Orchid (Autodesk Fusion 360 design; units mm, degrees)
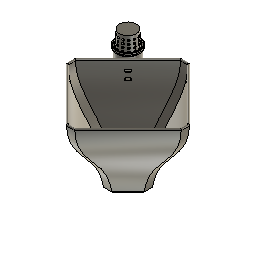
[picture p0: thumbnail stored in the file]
parameter "wall" = 1.35
parameter "height" = 102 (= "Size * 0.6") comment "Vase Hight (Medium setting)"
parameter "tolerance" = 0.15
sketch "Sketch1" plane through (0, 0, 0) normal (0, 0, 1) x axis (1, 0, 0)
  line L1 (-79.0621, -79.0621) -> (79.0621, -79.0621)
  line L2 (-79.0621, 79.0621) -> (-79.0621, -79.0621)
  line L3 (79.0621, 79.0621) -> (-79.0621, 79.0621)
  line L4 (79.0621, -79.0621) -> (79.0621, 79.0621)
  line L5 (-79.0621, 79.0621) -> (79.0621, -79.0621)
  line L6 (79.0621, 79.0621) -> (-79.0621, -79.0621)
  line L7 (-75.5266, 82.5976) -> (82.5976, -75.5266)
  line L8 (-82.5976, 75.5266) -> (75.5266, -82.5976)
  line L9 (-5.9379, 39.9379) -> (28.0621, 5.9379)
  line L10 (-39.9379, 5.9379) -> (-5.9379, 39.9379)
  line L11 (-5.9379, -28.0621) -> (-39.9379, 5.9379)
  line L12 (28.0621, 5.9379) -> (-5.9379, -28.0621)
  line L13 (-39.9379, 5.9379) -> (28.0621, 5.9379)
  line L14 (-5.9379, -28.0621) -> (-5.9379, 39.9379)
  line L15 (-5.9379, 79.0621) -> (-5.9379, 5.9379)
  line L16 (-2.4024, 9.4734) -> (-9.4734, 2.4024)
  line L17 (-60.5266, 67.5976) -> (-67.5976, 60.5266)
  circle C1 centre (-5.9379, 5.9379) radius 85
  circle C2 centre (-64.0621, 64.0621) radius 15
  circle C3 centre (-5.9379, 5.9379) radius 34
  circle C4 centre (-64.0621, 64.0621) radius 13.65
  circle C5 centre (-64.0621, 64.0621) radius 13.5
  circle C6 centre (-5.9379, 5.9379) radius 67.2
  point P6 (0, 0)
  point P1 (0, 0)
  point P7 (-5.9379, 5.9379)
  point P8 (-64.0621, 64.0621)
  point P9 (-5.9379, 5.9379)
  point P19 (-5.9379, 5.9379)
  point P15 (28.0621, 5.9379)
  point P20 (-5.9379, 5.9379)
  point P21 (-5.9379, 79.0621)
  point P22 (-9.4734, 2.4024)
  point P23 (-2.4024, 9.4734)
  point P26 (-5.9379, 5.9379)
  point P27 (-67.5976, 60.5266)
  point P28 (-60.5266, 67.5976)
  point P24 (-64.0621, 64.0621)
  horizontal L1
  perpendicular L1 L2
  parallel L1 L3
  parallel L2 L4
  coincident L5 P6
  coincident L6 P6
  coincident P1 P6
  coincident L5 P7
  coincident L5 P8
  tangent L3 C2
  tangent L4 C1
  coincident P7 P9
  perpendicular L9 L10
  parallel L9 L11
  parallel L10 L12
  coincident L13 P19
  coincident L14 P19
  coincident P9 P19
  equal L9 L12
  coincident C3 P15
  coincident P9 P20
  coincident L3 P21
  perpendicular L3 L15
  coincident L8 P22
  coincident L7 P23
  perpendicular L7 L16
  equal L2 L3
  midpoint P19 L16
  coincident P19 P26
  tangent C2 C6
  coincident L8 P27
  coincident L7 P28
  perpendicular L7 L17
  coincident P24 L17
  dimension "Size" diameter C1 = 170
  dimension "d5" diameter C2 = 30
  dimension "d8" = 5
  dimension "d9" = -5
  dimension "d16" = -51 (= "-Size * 0.3")
  dimension "d17" angle L13 L15 = 90
  dimension "d81" distance P7 P8 = 82.2 (= "Size * 0.42 + ( wall * 8 )")
work_plane "WorkPlane1" AlongDistance 25.5 (= "height / 4")
work_plane "WorkPlane2" AlongDistance 102 (= "height")
work_plane "WorkPlane5" AlongDistance 61.2 (= "height * 0.6")
work_plane "WorkPlane4" RotateAngle 90
sketch "Sketch2" plane through (0, 0, 25.5) normal (0, 0, 1) x axis (1, 0, 0)
  line L1 (-5.9379, 90.9379) -> (-5.9379, 5.9379)
  line L2 (-5.9379, 48.4379) -> (36.5621, 5.9379)
  line L3 (-48.4379, 5.9379) -> (-5.9379, 48.4379)
  line L4 (-5.9379, -36.5621) -> (-48.4379, 5.9379)
  line L5 (36.5621, 5.9379) -> (-5.9379, -36.5621)
  line L6 (-48.4379, 5.9379) -> (36.5621, 5.9379)
  line L7 (-5.9379, -36.5621) -> (-5.9379, 48.4379)
  circle C1 centre (-5.9379, 5.9379) radius 85
  circle C2 centre (-5.9379, 5.9379) radius 42.5
  point P2 (-5.9379, 5.9379)
  point P4 (-5.9379, 5.9379)
  point P5 (-5.9379, 90.9379)
  point P10 (-5.9379, 5.9379)
  point P6 (36.5621, 5.9379)
  coincident P2 P4
  coincident C1 P5
  vertical L1
  perpendicular L2 L3
  parallel L2 L4
  parallel L3 L5
  coincident L6 P10
  coincident L7 P10
  coincident P2 P10
  equal L2 L5
  coincident C2 P6
  dimension "d14" = -42.5 (= "-Size * 0.25")
  dimension "d15" angle L1 L6 = 90
sketch "Sketch3" plane through (0, 0, 102) normal (0, 0, 1) x axis (1, 0, 0)
  line L1 (-5.9379, 90.9379) -> (79.0621, 5.9379)
  line L2 (-90.9379, 5.9379) -> (-5.9379, 90.9379)
  line L3 (-5.9379, -79.0621) -> (-90.9379, 5.9379)
  line L4 (79.0621, 5.9379) -> (-5.9379, -79.0621)
  line L5 (-90.9379, 5.9379) -> (79.0621, 5.9379)
  line L6 (-5.9379, -79.0621) -> (-5.9379, 90.9379)
  line L7 (-5.9379, 90.9379) -> (-5.9379, 5.9379)
  circle C1 centre (-5.9379, 5.9379) radius 85
  circle C2 centre (-64.0621, 64.0621) radius 15
  circle C3 centre (-64.0621, 64.0621) radius 7.5
  point P7 (-5.9379, 5.9379)
  point P2 (-5.9379, 5.9379)
  point P3 (79.0621, 5.9379)
  point P8 (-5.9379, 5.9379)
  point P9 (-5.9379, 90.9379)
  perpendicular L1 L2
  parallel L1 L3
  parallel L2 L4
  coincident L5 P7
  coincident L6 P7
  coincident P2 P7
  equal L1 L4
  coincident C1 P3
  coincident P2 P8
  coincident C1 P9
  vertical L7
  concentric C2 C3
  dimension "d18" angle L5 L7 = 90
  dimension "d126" diameter C3 = 15
sketch "Sketch9" plane through (0, 0, 61.2) normal (0, 0, 1) x axis (1, 0, 0)
  circle C1 centre (-64.0621, 64.0621) radius 13.65
  circle C2 centre (-64.0621, 64.0621) radius 11
  concentric C1 C2
  dimension "d127" diameter C2 = 22
loft "Loft2" sketch "Sketch1" + "Sketch9" + "Sketch3" Start Weight 4.0298 Start TakeOff Angle 0 End Weight -3.9427 End TakeOff Angle 0
loft "Loft1" sketch "Sketch1" + "Sketch2" + "Sketch3" Start Weight 1.991 Start TakeOff Angle 0 End Weight -1.8239 End TakeOff Angle 0
chamfer "Chamfer4" distance 8
extrude "Extrude2" new body sketch "Sketch1" profile of C1 C2 L7 L8 C3 L9 L10 L16 C4 C5 C6 L17 blind 15 from offset 3
extrude "Extrude3" sketch "Sketch1" profile of C1 C2 L7 L8 C3 L9 L10 L16 C4 C5 C6 L17 blind -15 from offset -10
chamfer "Chamfer1" distance 1.35 (= "wall")
fillet "Fillet1" radius 3
extrude "Extrude17" sketch "Sketch1" profile of C1 L7 L8 C5 blind 20 taper -5
shell "Shell1" innerThickness 1.35 (= "wall")
extrude "Extrude18" add sketch "Sketch1" profile of C1 C2 L7 L8 C4 C5 along normal blind 20 taper -3
extrude "Extrude16" cut sketch "Sketch1" profile of C1 L7 L8 C4 C5 along normal blind 20 taper -5
offset_faces "OffsetFaces5" distance 1.35 (= "wall")
sketch "Sketch6" plane through (0, 0, 102) normal (0, 0, 1) x axis (-1, 0, 0)
  line L1 (64.0621, -47.5621) -> (64.0621, -80.5621)
  line L2 (56.3942, -49.4521) -> (71.73, -78.6721)
  line L3 (50.4829, -54.689) -> (77.6413, -73.4352)
  line L4 (47.6824, -62.0732) -> (80.4418, -66.0509)
  line L5 (48.6343, -69.9131) -> (79.4899, -58.2111)
  line L6 (53.1206, -76.4125) -> (75.0036, -51.7117)
  line L7 (60.1134, -80.0826) -> (68.0108, -48.0415)
  line L8 (68.0108, -80.0826) -> (60.1134, -48.0415)
  line L9 (75.0036, -76.4125) -> (53.1206, -51.7117)
  line L10 (79.4899, -69.9131) -> (48.6343, -58.2111)
  line L11 (80.4418, -62.0732) -> (47.6824, -66.0509)
  line L12 (77.6413, -54.689) -> (50.4829, -73.4352)
  line L13 (71.73, -49.4521) -> (56.3942, -78.6721)
  circle C1 centre (64.0621, -64.0621) radius 15.15
  circle C2 centre (64.0621, -64.0621) radius 16.5
  circle C3 centre (64.0621, -64.0621) radius 12.3
  circle C4 centre (64.0621, -64.0621) radius 15
  circle C5 centre (64.0621, -64.0621) radius 13.65
  point P5 (64.0621, -80.5621)
  point P6 (64.0621, -47.5621)
  point P3 (64.0621, -64.0621)
  coincident C2 P5
  coincident C2 P6
  vertical L1
  coincident P3 L1
  concentric C2 C4
  concentric C3 C5
  dimension "d115" distance C1 C2 = 1.35 (= "wall")
  dimension "d140" distance C1 C4 = 0.15 (= "tolerance")
  dimension "d141" distance C3 C5 = 1.35 (= "wall")
  dimension "d74" C-Pattern1-Angle = 360
extrude "Extrude7" add sketch "Sketch6" profile of C1 C2 C3 L1 L2 L3 L4 L5 L6 L7 L8 L9 L10 L11 L12 L13 no distance stored
extrude "Extrude6" add sketch "Sketch6" profile of C1 C2 L1 L2 L3 L4 L5 L6 L7 L8 L9 L10 L11 L12 L13 along normal blind 2 taper -5
extrude "Extrude8" cut sketch "Sketch6" profile of C3 L1 L2 L3 L4 L5 L6 L7 L8 L9 L10 L11 L12 L13 C5 along normal blind 2.5
rectangular_pattern "R-Pattern1" uSpaceDistance 4.5 vSpaceDistance 0
chamfer "Chamfer5" distance 0.8
circular_pattern "C-Pattern1" countU 13 TotalAngle 360
chamfer "Chamfer7" distance 2.7 (= "wall * 2") distance 1.5 (= "wall + tolerance")
sketch "Sketch7" plane through (-5.9379, 5.9379, 0) normal (0.7071, -0.7071, 0) x axis (0.7071, 0.7071, 0)
  line L1 (3.65, 6) -> (3.65, 15)
  line L2 (-3.65, 15) -> (-3.65, 6)
  line L3 (5, 15) -> (5, 6)
  line L4 (-5, 6) -> (-5, 15)
  line L5 (-3.65, 89) -> (-3.65, 80)
  line L6 (3.65, 80) -> (3.65, 89)
  line L7 (5, 89) -> (5, 80)
  line L8 (-5, 80) -> (-5, 89)
  line L9 (-2, 4.35) -> (2, 4.35)
  line L10 (2, 16.65) -> (-2, 16.65)
  line L11 (2, 3) -> (-2, 3)
  line L12 (-2, 18) -> (2, 18)
  line L13 (-2, 78.35) -> (2, 78.35)
  line L14 (2, 90.65) -> (-2, 90.65)
  line L15 (-2, 92) -> (2, 92)
  line L16 (2, 77) -> (-2, 77)
  line L17 (2, 80) -> (-2, 89)
  line L18 (2, 6) -> (-2, 15)
  line L19 (2, 87.35) -> (-2, 87.35)
  line L20 (2, 81.65) -> (-2, 81.65)
  line L21 (2, 13.35) -> (-2, 13.35)
  line L22 (2, 7.65) -> (-2, 7.65)
  arc A1 centre (-2, 6) radius 1.65 clockwise from (-2, 4.35) to (-3.65, 6)
  arc A2 centre (-2, 15) radius 1.65 clockwise from (-3.65, 15) to (-2, 16.65)
  arc A3 centre (-2, 6) radius 3 clockwise from (-2, 3) to (-5, 6)
  arc A4 centre (-2, 15) radius 3 clockwise from (-5, 15) to (-2, 18)
  arc A5 centre (2, 80) radius 1.65 clockwise from (3.65, 80) to (2, 78.35)
  arc A6 centre (2, 89) radius 1.65 clockwise from (2, 90.65) to (3.65, 89)
  arc A7 centre (2, 80) radius 3 clockwise from (5, 80) to (2, 77)
  arc A8 centre (2, 89) radius 3 clockwise from (2, 92) to (5, 89)
  arc A9 centre (2, 6) radius 1.65 clockwise from (3.65, 6) to (2, 4.35)
  arc A10 centre (2, 15) radius 1.65 clockwise from (2, 16.65) to (3.65, 15)
  arc A11 centre (2, 6) radius 3 clockwise from (5, 6) to (2, 3)
  arc A12 centre (2, 15) radius 3 clockwise from (2, 18) to (5, 15)
  arc A13 centre (-2, 80) radius 1.65 clockwise from (-2, 78.35) to (-3.65, 80)
  arc A14 centre (-2, 89) radius 1.65 clockwise from (-3.65, 89) to (-2, 90.65)
  arc A15 centre (-2, 89) radius 3 clockwise from (-5, 89) to (-2, 92)
  arc A16 centre (-2, 80) radius 3 clockwise from (-2, 77) to (-5, 80)
  circle C1 centre (2, 89) radius 1.65
  circle C2 centre (-2, 89) radius 1.65
  circle C3 centre (-2, 80) radius 1.65
  circle C4 centre (2, 80) radius 1.65
  circle C5 centre (0, 84.5) radius 1.65
  circle C6 centre (2, 15) radius 1.65
  circle C7 centre (-2, 15) radius 1.65
  circle C8 centre (-2, 6) radius 1.65
  circle C9 centre (2, 6) radius 1.65
  circle C10 centre (0, 10.5) radius 1.65
  point P39 (-2, 89)
  point P42 (-2, 89)
  point P20 (2, 80)
  point P43 (2, 80)
  point P19 (-2, 15)
  point P44 (-2, 15)
  point P27 (2, 6)
  point P45 (2, 6)
  point P49 (2, 80)
  point P50 (0, 84.5)
  point P52 (-2, 15)
  point P54 (2, 6)
  point P55 (0, 10.5)
  point P56 (-2, 87.35)
  point P57 (2, 87.35)
  point P58 (-2, 81.65)
  point P59 (2, 81.65)
  point P60 (-2, 13.35)
  point P61 (2, 13.35)
  point P62 (-2, 7.65)
  point P63 (2, 7.65)
  point P11 (2, 90.65)
  point P18 (-2, 6)
  point P53 (-2, 6)
  coincident P39 P42
  coincident P20 P43
  coincident P19 P44
  coincident P27 P45
  concentric A6 C1
  concentric A14 C2
  concentric A13 C3
  coincident P43 P49
  midpoint L17 P50
  concentric A10 C6
  coincident P44 P52
  coincident P45 P54
  midpoint L18 P55
  equal C1 C2
  equal C1 C5
  equal C1 C4
  equal C1 C3
  equal C1 C6
  equal C1 C7
  equal C1 C10
  equal C1 C9
  equal C1 C8
  coincident C2 P56
  coincident C1 P57
  tangent C1 L19
  horizontal L19
  coincident C3 P58
  coincident C4 P59
  tangent C4 L20
  parallel L19 L20
  coincident C7 P60
  coincident C6 P61
  tangent C6 L21
  parallel L20 L21
  coincident C8 P62
  coincident C9 P63
  tangent C9 L22
  parallel L21 L22
  coincident P11 C1
  coincident P18 P53
extrude "Extrude19" cut sketch "Sketch7" profile of L1 L2 L5 L6 A1 A2 A5 A6 A9 L9 L10 A10 L13 A13 A14 L14 C1 C2 C3 C4 C5 C6 C7 C8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 against normal blind 82.2 (magnitude of "-d81")
extrude "Extrude14" cut sketch "Sketch7" profile of A1 A2 A5 A6 A9 L9 L10 A10 L13 A13 A14 L14 C1 C2 C3 C4 C6 C7 C8 C9 L19 L20 L21 L22 against normal blind 85 (magnitude of "-Size / 2")
combine "Combine6"
remove_body "RemoveBody21"
remove_body "RemoveBody22"
combine "Combine7"
remove_body "RemoveBody25"
remove_body "RemoveBody27"
sketch "Sketch8" plane through (0, 0, 0) normal (0.7071, 0.7071, 0) x axis (-0.7071, 0.7071, 0)
  line L1 (103.1951, 81.3215) -> (78.7657, 77.0139)
  line L2 (43.0145, 66.35) -> (18.2875, 66.35)
  line L3 (103.1951, 81.3215) -> (103.1951, 82.6923)
  line L4 (103.1951, 82.6923) -> (78.5685, 78.35)
  curve K1 (103.8915, 20) -> (104.2073, 97.9502)
  curve K2 (78.5685, 78.35) -> (77.3035, 20)
  curve K3 (76.9876, 97.9502) -> (77.2864, 90.65)
  point P6 (103.1951, 82.6923)
  point P5 (78.5685, 78.35)
  point P10 (78.5685, 78.35)
  point P13 (78.7657, 77.0139)
  point P2 (18.2875, 66.35)
  horizontal L2
  parallel L1 L4
  vertical L3
  coincident P6 K1
  coincident P5 P10
  coincident K2 P13
  coincident P2 L1
  dimension "d84" angle L1 L2 = 10
  dimension "d136" distance L1 L4 = 1.35 (= "wall")
extrude "Extrude11" new body sketch "Sketch8" profile of L1 L3 L4 distance 20
combine "Combine5"
remove_body "RemoveBody9"
remove_body "RemoveBody14"
work_plane "WorkPlane3" RotateAngle 90
sketch "Sketch5" plane through (-5.9379, 30, 100) normal (1, 0, 0) x axis (0, 1, 0)
  line L1 (53.9311, 2) -> (55.2811, 2)
  line L2 (54.6061, 1.2) -> (54.6061, 2)
  line L3 (-18.9644, 2) -> (53.9311, 2)
  line L4 (60.9379, 2) -> (-24.0621, 2)
  circle C1 centre (54.6061, 1.2) radius 1.25
  point P2 (55.2811, 2)
  point P3 (53.9311, 2)
  point P5 (54.6061, 2)
  point P4 (54.6061, 1.2)
  point P6 (54.6061, 1.2)
  point P7 (53.9311, 2)
  coincident P2 L4
  coincident P3 L3
  midpoint L1 P5
  perpendicular L1 L2
  coincident P4 P6
  coincident P3 P7
  dimension "d36" diameter C1 = 2.5
  dimension "d135" distance P5 P6 = 0.8
sweep "Sweep1" sketch "Sketch5" TwistAngle 0 TaperAngle 0
combine "Combine8"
